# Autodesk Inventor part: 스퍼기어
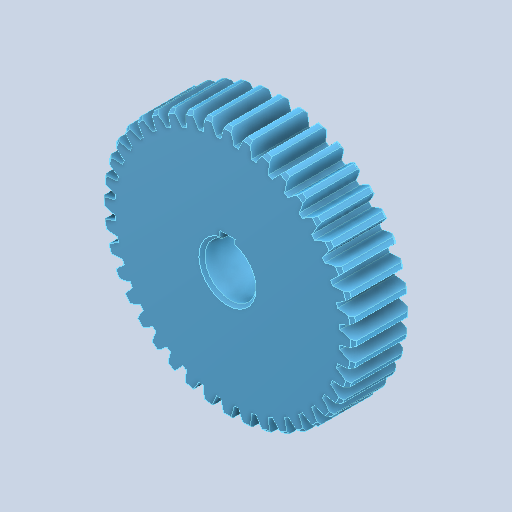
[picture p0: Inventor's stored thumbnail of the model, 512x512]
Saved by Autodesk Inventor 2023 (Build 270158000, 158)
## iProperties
Created: 2025-03
Part Number: 스퍼기어
Material: 알루미늄 6061
Document SubType Name: Modeling
Designer: user
Density: 2.71 g/cm^3
Appearance: 기본값
Author: jhkim
Sending System: Autodesk Inventor 2025
Preprocessor: ST-DEVELOPER v20
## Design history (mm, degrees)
feature "Solid1"
node "솔리드1"
